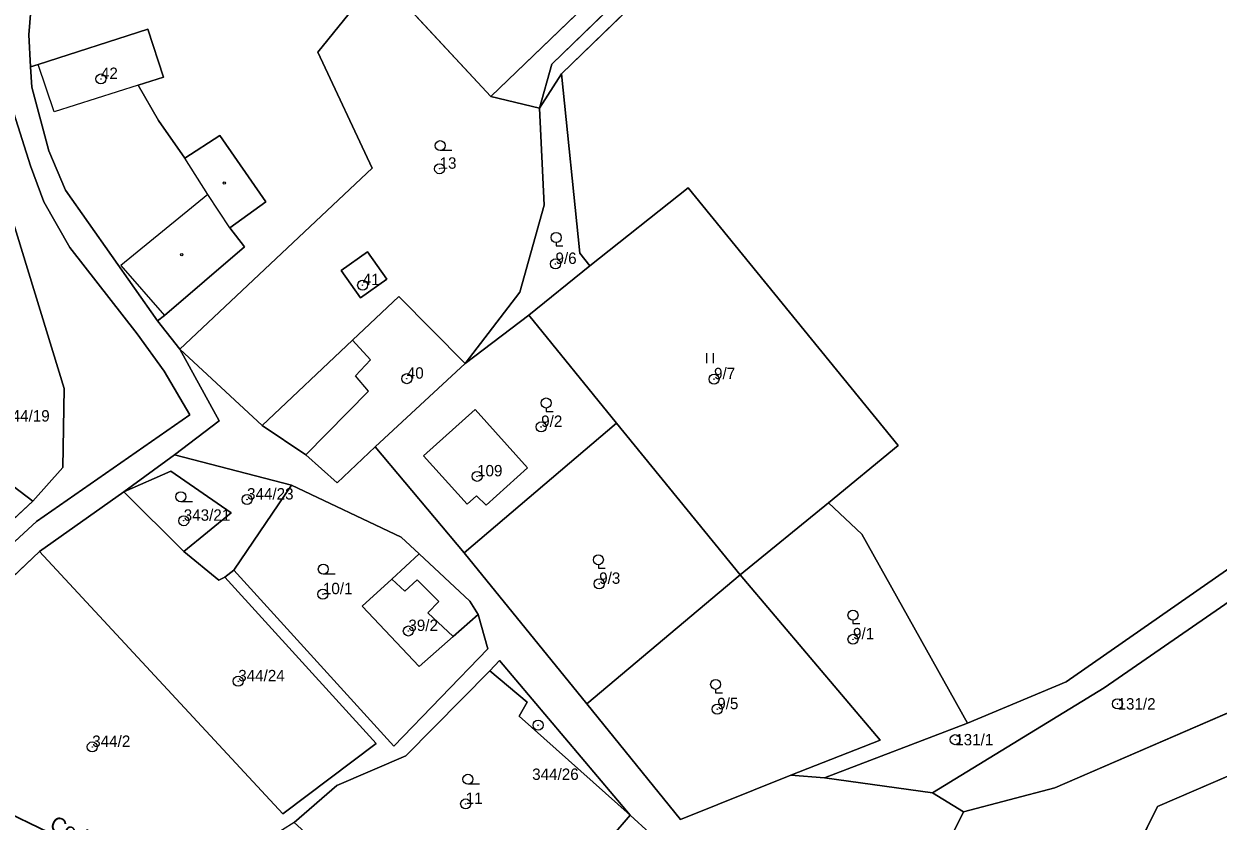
# Model space of a CAD drawing. Extents: x -652854 to -650068, y -1097661 to -1095417.
# Drawn here: x -650819.6 to -650641.1, y -1095957.3 to -1095838.2 of the extents above; entities that cross this region are included whole.
import ezdxf

# ---------------------------------------------------------------- set-up
doc = ezdxf.new("R2010")
doc.units = 0
for name, color, linetype in [('Definiční body parcel', 7, 'Continuous'), ('Hranice - vnitř_ kresba', 7, 'Continuous'), ('Hranice parcel', 7, 'Continuous'), ('Názvy', 7, 'Continuous'), ('Obvody jako plochy', 7, 'Continuous'), ('Parcelní čísla', 7, 'Continuous'), ('Prvky pro prodl_ par_ č_', 7, 'Continuous'), ('Značky kultur', 7, 'Continuous'), ('Značky na budově ne v SPI', 7, 'Continuous')]:
    doc.layers.add(name, color=color, linetype=linetype)

msp = doc.modelspace()

# ---------------------------------------------------------------- linework, layer by layer
at = {"layer": 'Definiční body parcel'}
for centre, radius in [((-650808.08, -1095846.43), 0.75), ((-650808.08, -1095846.43), 0.0327), ((-650757.46, -1095859.84), 0.75), ((-650757.46, -1095859.84), 0.0327), ((-650740.14, -1095874.06), 0.75), ((-650740.14, -1095874.06), 0.0327), ((-650768.96, -1095877.23), 0.75), ((-650768.96, -1095877.23), 0.0327), ((-650762.36, -1095891.2), 0.75), ((-650716.44, -1095891.27), 0.75), ((-650762.36, -1095891.2), 0.0327), ((-650716.44, -1095891.27), 0.0327), ((-650742.28, -1095898.4), 0.75), ((-650742.28, -1095898.4), 0.0327), ((-650751.86, -1095905.79), 0.75), ((-650751.86, -1095905.79), 0.0327), ((-650786.24, -1095909.25), 0.75), ((-650786.24, -1095909.25), 0.0327), ((-650795.7, -1095912.42), 0.75), ((-650795.7, -1095912.42), 0.0327), ((-650733.61, -1095921.84), 0.75), ((-650774.9, -1095923.39), 0.75), ((-650733.61, -1095921.84), 0.0327), ((-650774.9, -1095923.39), 0.0327), ((-650762.13, -1095928.89), 0.75), ((-650762.13, -1095928.89), 0.0327), ((-650695.67, -1095930.13), 0.75), ((-650695.67, -1095930.13), 0.0327), ((-650787.56, -1095936.4), 0.75), ((-650787.56, -1095936.4), 0.0327), ((-650715.96, -1095940.57), 0.75), ((-650715.96, -1095940.57), 0.0327), ((-650656.13, -1095939.77), 0.75), ((-650656.13, -1095939.77), 0.0327), ((-650742.74, -1095942.96), 0.75), ((-650742.74, -1095942.96), 0.0327), ((-650809.38, -1095946.2), 0.75), ((-650680.39, -1095945.12), 0.75), ((-650680.39, -1095945.12), 0.0327), ((-650809.38, -1095946.2), 0.0327), ((-650753.56, -1095954.72), 0.75), ((-650753.56, -1095954.72), 0.0327)]:
    msp.add_circle(centre, radius, dxfattribs=at)
at = {"layer": 'Hranice - vnitř_ kresba'}
for p, q in [((-650815.06, -1095851.32), (-650817.44, -1095844.26)), ((-650802.53, -1095847.35), (-650815.06, -1095851.32)), ((-650792.11, -1095863.7), (-650795.54, -1095858.28)), ((-650792.11, -1095863.7), (-650805.08, -1095874.27)), ((-650788.83, -1095868.66), (-650792.11, -1095863.7)), ((-650805.08, -1095874.27), (-650798.57, -1095881.77)), ((-650767.77, -1095888.38), (-650770.5, -1095885.45)), ((-650770.05, -1095890.78), (-650767.77, -1095888.38)), ((-650768.07, -1095893.06), (-650770.05, -1095890.78)), ((-650777.46, -1095902.58), (-650768.07, -1095893.06)), ((-650764.61, -1095921.13), (-650762.66, -1095922.94)), ((-650762.66, -1095922.94), (-650760.83, -1095921.27)), ((-650760.83, -1095921.27), (-650757.56, -1095924.49)), ((-650757.56, -1095924.49), (-650759.21, -1095926.2)), ((-650759.21, -1095926.2), (-650755.43, -1095929.71))]:
    msp.add_line(p, q, dxfattribs=at)
at = {"layer": 'Hranice parcel'}
for p, q in [((-650749.82, -1095849.06), (-650710.55, -1095811.33)), ((-650818.83, -1095839.82), (-650816.69, -1095813.37)), ((-650707.91, -1095812.42), (-650740.66, -1095844.24)), ((-650707.4, -1095814.79), (-650739.26, -1095845.66)), ((-650775.65, -1095842.44), (-650766.51, -1095831.07)), ((-650766.51, -1095831.07), (-650749.82, -1095849.06)), ((-650817.44, -1095844.26), (-650801.07, -1095838.98)), ((-650801.07, -1095838.98), (-650798.74, -1095846.16)), ((-650818.59, -1095844.63), (-650818.83, -1095839.82)), ((-650767.52, -1095859.75), (-650775.65, -1095842.44)), ((-650818.59, -1095844.63), (-650817.44, -1095844.26)), ((-650740.66, -1095844.24), (-650742.53, -1095850.77)), ((-650818.41, -1095847.67), (-650818.59, -1095844.63)), ((-650742.53, -1095850.77), (-650739.26, -1095845.66)), ((-650739.26, -1095845.66), (-650736.48, -1095872.46)), ((-650822.33, -1095847.63), (-650818.61, -1095859.41)), ((-650815.85, -1095857.15), (-650818.41, -1095847.67)), ((-650798.74, -1095846.16), (-650802.53, -1095847.35)), ((-650802.53, -1095847.35), (-650799.45, -1095852.64)), ((-650742.53, -1095850.77), (-650749.82, -1095849.06)), ((-650741.85, -1095865.29), (-650742.53, -1095850.77)), ((-650799.45, -1095852.64), (-650795.54, -1095858.28)), ((-650795.54, -1095858.28), (-650790.32, -1095854.86)), ((-650790.32, -1095854.86), (-650783.41, -1095864.8)), ((-650813.36, -1095863.05), (-650815.85, -1095857.15)), ((-650818.61, -1095859.41), (-650816.62, -1095864.78)), ((-650767.52, -1095859.75), (-650796.27, -1095886.77)), ((-650813.57, -1095892.69), (-650822.42, -1095863.74)), ((-650799.6, -1095882.56), (-650813.36, -1095863.05)), ((-650734.98, -1095874.35), (-650720.3, -1095862.69)), ((-650720.3, -1095862.69), (-650688.9, -1095901.19)), ((-650816.62, -1095864.78), (-650812.74, -1095871.62)), ((-650783.41, -1095864.8), (-650788.83, -1095868.66)), ((-650745.45, -1095878.26), (-650741.85, -1095865.29)), ((-650788.83, -1095868.66), (-650786.61, -1095871.49)), ((-650812.74, -1095871.62), (-650802.65, -1095884.5)), ((-650786.61, -1095871.49), (-650798.57, -1095881.77)), ((-650768.24, -1095872.24), (-650772.18, -1095875.06)), ((-650765.35, -1095876.35), (-650768.24, -1095872.24)), ((-650736.48, -1095872.46), (-650734.98, -1095874.35)), ((-650734.98, -1095874.35), (-650744.11, -1095881.7)), ((-650772.18, -1095875.06), (-650769.26, -1095879.11)), ((-650769.26, -1095879.11), (-650765.35, -1095876.35)), ((-650753.65, -1095888.94), (-650745.45, -1095878.26)), ((-650770.5, -1095885.45), (-650763.57, -1095878.9)), ((-650763.57, -1095878.9), (-650753.65, -1095888.94)), ((-650798.57, -1095881.77), (-650799.6, -1095882.56)), ((-650744.11, -1095881.7), (-650753.65, -1095888.94)), ((-650744.11, -1095881.7), (-650731, -1095897.82)), ((-650796.27, -1095886.77), (-650799.6, -1095882.56)), ((-650802.65, -1095884.5), (-650798.62, -1095890.09)), ((-650790.39, -1095897.52), (-650796.27, -1095886.77)), ((-650796.27, -1095886.77), (-650783.98, -1095898.17)), ((-650783.98, -1095898.17), (-650770.5, -1095885.45)), ((-650753.65, -1095888.94), (-650767.09, -1095901.36)), ((-650844.78, -1095889.35), (-650818.25, -1095909.52)), ((-650798.62, -1095890.09), (-650794.81, -1095896.6)), ((-650813.78, -1095904.48), (-650813.57, -1095892.69)), ((-650752.16, -1095895.79), (-650759.84, -1095902.7)), ((-650744.32, -1095904.5), (-650752.16, -1095895.79)), ((-650794.81, -1095896.6), (-650817.71, -1095912.52)), ((-650797.09, -1095902.55), (-650790.39, -1095897.52)), ((-650753.8, -1095917.19), (-650731, -1095897.82)), ((-650731, -1095897.82), (-650712.52, -1095920.49)), ((-650777.46, -1095902.58), (-650783.98, -1095898.17)), ((-650767.09, -1095901.36), (-650772.79, -1095906.75)), ((-650753.8, -1095917.19), (-650767.09, -1095901.36)), ((-650688.9, -1095901.19), (-650699.31, -1095909.75)), ((-650804.63, -1095908.11), (-650797.09, -1095902.55)), ((-650797.09, -1095902.55), (-650779.6, -1095907.12)), ((-650772.79, -1095906.75), (-650777.46, -1095902.58)), ((-650759.84, -1095902.7), (-650753.32, -1095909.94)), ((-650615.21, -1095902.66), (-650663.79, -1095936.46)), ((-650818.25, -1095909.52), (-650813.78, -1095904.48)), ((-650797.61, -1095905), (-650804.63, -1095908.11)), ((-650788.6, -1095911.24), (-650797.61, -1095905)), ((-650750.52, -1095910.09), (-650744.32, -1095904.5)), ((-650817.24, -1095917.02), (-650804.63, -1095908.11)), ((-650804.63, -1095908.11), (-650795.71, -1095917.03)), ((-650788.22, -1095919.78), (-650779.6, -1095907.12)), ((-650779.6, -1095907.12), (-650763.22, -1095914.85)), ((-650830.74, -1095921.05), (-650818.25, -1095909.52)), ((-650753.32, -1095909.94), (-650751.96, -1095908.72)), ((-650751.96, -1095908.72), (-650750.52, -1095910.09)), ((-650712.52, -1095920.49), (-650699.31, -1095909.75)), ((-650694.36, -1095914.44), (-650699.31, -1095909.75)), ((-650795.71, -1095917.03), (-650788.6, -1095911.24)), ((-650817.71, -1095912.52), (-650843.42, -1095936.19)), ((-650763.22, -1095914.85), (-650760.52, -1095917.37)), ((-650678.58, -1095942.65), (-650694.36, -1095914.44)), ((-650840.77, -1095939.29), (-650817.24, -1095917.02)), ((-650780.89, -1095956.2), (-650817.24, -1095917.02)), ((-650795.71, -1095917.03), (-650790.44, -1095921.28)), ((-650760.52, -1095917.37), (-650764.61, -1095921.13)), ((-650760.52, -1095917.37), (-650752.95, -1095924.41)), ((-650735.43, -1095939.77), (-650753.8, -1095917.19)), ((-650790.44, -1095921.28), (-650789.54, -1095920.86)), ((-650789.54, -1095920.86), (-650788.22, -1095919.78)), ((-650789.54, -1095920.86), (-650766.95, -1095945.69)), ((-650764.3, -1095946.11), (-650788.22, -1095919.78)), ((-650712.52, -1095920.49), (-650735.43, -1095939.77)), ((-650691.59, -1095945.18), (-650712.52, -1095920.49)), ((-650633.81, -1095920.58), (-650658.15, -1095937.4)), ((-650764.61, -1095921.13), (-650769.01, -1095925.17)), ((-650752.95, -1095924.41), (-650751.71, -1095926.43)), ((-650769.01, -1095925.17), (-650760.51, -1095934.19)), ((-650755.43, -1095929.71), (-650751.71, -1095926.43)), ((-650751.71, -1095926.43), (-650750.24, -1095931.56)), ((-650760.51, -1095934.19), (-650755.43, -1095929.71)), ((-650750.24, -1095931.56), (-650764.3, -1095946.11)), ((-650749.95, -1095934.85), (-650748.52, -1095933.28)), ((-650748.52, -1095933.28), (-650728.99, -1095956.42)), ((-650749.95, -1095934.85), (-650762.5, -1095947.53)), ((-650744.35, -1095939.5), (-650749.95, -1095934.85)), ((-650624.51, -1095934.57), (-650665.5, -1095952.31)), ((-650663.79, -1095936.46), (-650678.58, -1095942.65)), ((-650658.15, -1095937.4), (-650683.81, -1095953.04)), ((-650745.59, -1095941.61), (-650744.35, -1095939.5)), ((-650735.43, -1095939.77), (-650721.47, -1095957.06)), ((-650728.99, -1095956.42), (-650745.59, -1095941.61)), ((-650678.58, -1095942.65), (-650699.94, -1095950.82)), ((-650766.95, -1095945.69), (-650780.89, -1095956.2)), ((-650704.97, -1095950.42), (-650691.59, -1095945.18)), ((-650626.69, -1095945), (-650650.16, -1095955.09)), ((-650762.5, -1095947.53), (-650772.84, -1095951.98)), ((-650721.47, -1095957.06), (-650704.97, -1095950.42)), ((-650704.97, -1095950.42), (-650699.94, -1095950.82)), ((-650683.81, -1095953.04), (-650699.94, -1095950.82)), ((-650828.97, -1095952.68), (-650768.13, -1095982)), ((-650772.84, -1095951.98), (-650779.21, -1095957.51)), ((-650679.13, -1095955.92), (-650683.81, -1095953.04)), ((-650665.5, -1095952.31), (-650679.13, -1095955.92)), ((-650731.74, -1095959.61), (-650728.99, -1095956.42)), ((-650726.02, -1095959.09), (-650728.99, -1095956.42)), ((-650679.13, -1095955.92), (-650683.21, -1095964.08)), ((-650650.16, -1095955.09), (-650655.71, -1095966.27))]:
    msp.add_line(p, q, dxfattribs=at)
at = {"layer": 'Obvody jako plochy'}
for points in [[(-650715.92, -1095779.02), (-650707.91, -1095812.42), (-650740.66, -1095844.24), (-650742.53, -1095850.77), (-650739.26, -1095845.66), (-650707.4, -1095814.79), (-650699.64, -1095816.89), (-650709.03, -1095779.57), (-650692.25, -1095742.86)], [(-650715.92, -1095779.02), (-650733.52, -1095789.9), (-650720.49, -1095784.94), (-650710.55, -1095811.33), (-650749.82, -1095849.06), (-650742.53, -1095850.77), (-650740.66, -1095844.24), (-650707.91, -1095812.42)], [(-650749.82, -1095849.06), (-650710.55, -1095811.33), (-650720.49, -1095784.94), (-650733.52, -1095789.9), (-650762.13, -1095825.6), (-650766.51, -1095831.07)], [(-650822.33, -1095847.63), (-650821.45, -1095812.61), (-650825.74, -1095811.08), (-650838.32, -1095807.2), (-650848.05, -1095802.48), (-650850.5, -1095805.49), (-650871.31, -1095836.39), (-650885.3, -1095832.78), (-650888.99, -1095851.28), (-650843.17, -1095879.48), (-650857.68, -1095897.96), (-650846.23, -1095925.14), (-650850.06, -1095928.49), (-650843.42, -1095936.19), (-650817.71, -1095912.52), (-650794.81, -1095896.6), (-650798.62, -1095890.09), (-650802.65, -1095884.5), (-650812.74, -1095871.62), (-650816.62, -1095864.78), (-650818.61, -1095859.41)], [(-650742.53, -1095850.77), (-650749.82, -1095849.06), (-650766.51, -1095831.07), (-650775.65, -1095842.44), (-650767.52, -1095859.75), (-650796.27, -1095886.77), (-650783.98, -1095898.17), (-650770.5, -1095885.45), (-650763.57, -1095878.9), (-650753.65, -1095888.94), (-650745.45, -1095878.26), (-650741.85, -1095865.29)], [(-650813.36, -1095863.05), (-650799.6, -1095882.56), (-650798.57, -1095881.77), (-650786.61, -1095871.49), (-650788.83, -1095868.66), (-650783.41, -1095864.8), (-650790.32, -1095854.86), (-650795.54, -1095858.28), (-650799.45, -1095852.64), (-650802.53, -1095847.35), (-650798.74, -1095846.16), (-650801.07, -1095838.98), (-650817.44, -1095844.26), (-650818.59, -1095844.63), (-650818.41, -1095847.67), (-650815.85, -1095857.15)], [(-650742.53, -1095850.77), (-650741.85, -1095865.29), (-650745.45, -1095878.26), (-650753.65, -1095888.94), (-650744.11, -1095881.7), (-650734.98, -1095874.35), (-650736.48, -1095872.46), (-650739.26, -1095845.66)], [(-650830.74, -1095921.05), (-650844.06, -1095898.11), (-650844.78, -1095889.35), (-650831, -1095870.58), (-650822.42, -1095863.74), (-650813.57, -1095892.69), (-650813.78, -1095904.48), (-650818.25, -1095909.52)], [(-650844.78, -1095889.35), (-650818.25, -1095909.52), (-650813.78, -1095904.48), (-650813.57, -1095892.69), (-650822.42, -1095863.74), (-650831, -1095870.58)], [(-650734.98, -1095874.35), (-650744.11, -1095881.7), (-650731, -1095897.82), (-650712.52, -1095920.49), (-650699.31, -1095909.75), (-650688.9, -1095901.19), (-650720.3, -1095862.69)], [(-650768.24, -1095872.24), (-650772.18, -1095875.06), (-650769.26, -1095879.11), (-650765.35, -1095876.35)], [(-650768.24, -1095872.24), (-650765.35, -1095876.35), (-650769.26, -1095879.11), (-650772.18, -1095875.06)], [(-650777.46, -1095902.58), (-650772.79, -1095906.75), (-650767.09, -1095901.36), (-650753.65, -1095888.94), (-650763.57, -1095878.9), (-650770.5, -1095885.45), (-650783.98, -1095898.17)], [(-650744.11, -1095881.7), (-650753.65, -1095888.94), (-650767.09, -1095901.36), (-650753.8, -1095917.19), (-650731, -1095897.82)], [(-650830.74, -1095921.05), (-650818.25, -1095909.52), (-650844.78, -1095889.35), (-650844.06, -1095898.11)], [(-650752.16, -1095895.79), (-650759.84, -1095902.7), (-650753.32, -1095909.94), (-650751.96, -1095908.72), (-650750.52, -1095910.09), (-650744.32, -1095904.5)], [(-650752.16, -1095895.79), (-650744.32, -1095904.5), (-650750.52, -1095910.09), (-650751.96, -1095908.72), (-650753.32, -1095909.94), (-650759.84, -1095902.7)], [(-650735.43, -1095939.77), (-650712.52, -1095920.49), (-650731, -1095897.82), (-650753.8, -1095917.19)], [(-650602.74, -1095899.15), (-650615.21, -1095902.66), (-650663.79, -1095936.46), (-650678.58, -1095942.65), (-650699.94, -1095950.82), (-650683.81, -1095953.04), (-650658.15, -1095937.4), (-650633.81, -1095920.58)], [(-650797.61, -1095905), (-650788.6, -1095911.24), (-650795.71, -1095917.03), (-650790.44, -1095921.28), (-650789.54, -1095920.86), (-650788.22, -1095919.78), (-650779.6, -1095907.12), (-650797.09, -1095902.55), (-650804.63, -1095908.11)], [(-650797.61, -1095905), (-650804.63, -1095908.11), (-650795.71, -1095917.03), (-650788.6, -1095911.24)], [(-650817.24, -1095917.02), (-650780.89, -1095956.2), (-650766.95, -1095945.69), (-650789.54, -1095920.86), (-650790.44, -1095921.28), (-650795.71, -1095917.03), (-650804.63, -1095908.11)], [(-650779.6, -1095907.12), (-650788.22, -1095919.78), (-650764.3, -1095946.11), (-650750.24, -1095931.56), (-650751.71, -1095926.43), (-650755.43, -1095929.71), (-650760.51, -1095934.19), (-650769.01, -1095925.17), (-650764.61, -1095921.13), (-650760.52, -1095917.37), (-650763.22, -1095914.85)], [(-650704.97, -1095950.42), (-650699.94, -1095950.82), (-650678.58, -1095942.65), (-650694.36, -1095914.44), (-650699.31, -1095909.75), (-650712.52, -1095920.49), (-650691.59, -1095945.18)], [(-650760.52, -1095917.37), (-650764.61, -1095921.13), (-650769.01, -1095925.17), (-650760.51, -1095934.19), (-650755.43, -1095929.71), (-650751.71, -1095926.43), (-650752.95, -1095924.41)], [(-650704.97, -1095950.42), (-650691.59, -1095945.18), (-650712.52, -1095920.49), (-650735.43, -1095939.77), (-650721.47, -1095957.06)], [(-650624.51, -1095934.57), (-650633.81, -1095920.58), (-650658.15, -1095937.4), (-650683.81, -1095953.04), (-650679.13, -1095955.92), (-650665.5, -1095952.31)], [(-650749.95, -1095934.85), (-650744.35, -1095939.5), (-650745.59, -1095941.61), (-650728.99, -1095956.42), (-650748.52, -1095933.28)], [(-650779.21, -1095957.51), (-650772.12, -1095963.94), (-650768.45, -1095961.71), (-650765.09, -1095964.36), (-650758.42, -1095965.5), (-650751.99, -1095963.16), (-650731.74, -1095959.61), (-650728.99, -1095956.42), (-650745.59, -1095941.61), (-650744.35, -1095939.5), (-650749.95, -1095934.85), (-650762.5, -1095947.53), (-650772.84, -1095951.98)], [(-650681.34, -1095998.35), (-650674.69, -1096001.79), (-650675.32, -1096003.13), (-650663.2, -1096025.43), (-650655.69, -1095990.58), (-650655.71, -1095966.27), (-650650.16, -1095955.09), (-650626.69, -1095945), (-650627.52, -1095958.3), (-650612.04, -1095953.51), (-650623.58, -1095936.04), (-650624.51, -1095934.57), (-650665.5, -1095952.31), (-650679.13, -1095955.92), (-650683.21, -1095964.08), (-650673.46, -1095966.76), (-650685.7, -1095992.01), (-650687.25, -1095993.74), (-650697.45, -1096004.89), (-650687.41, -1096010.3)], [(-650613.9, -1096078.29), (-650593.69, -1096090.8), (-650580.06, -1096067.29), (-650611.4, -1096015.81), (-650627.52, -1095958.3), (-650626.69, -1095945), (-650650.16, -1095955.09), (-650655.71, -1095966.27), (-650655.69, -1095990.58), (-650663.2, -1096025.43), (-650644.26, -1096049.61)], [(-650779.21, -1095971.99), (-650730.24, -1095960.69), (-650726.02, -1095959.09), (-650728.99, -1095956.42), (-650731.74, -1095959.61), (-650751.99, -1095963.16), (-650758.42, -1095965.5), (-650765.09, -1095964.36), (-650768.45, -1095961.71), (-650772.12, -1095963.94), (-650779.21, -1095957.51), (-650787.92, -1095962.98)]]:
    msp.add_lwpolyline(points, close=True, dxfattribs=at)
for points in [[(-650840.77, -1095939.29), (-650817.24, -1095917.02), (-650804.63, -1095908.11), (-650797.09, -1095902.55), (-650790.39, -1095897.52), (-650796.27, -1095886.77), (-650799.6, -1095882.56), (-650813.36, -1095863.05), (-650815.85, -1095857.15), (-650818.41, -1095847.67), (-650818.59, -1095844.63), (-650818.83, -1095839.82), (-650816.69, -1095813.37), (-650820.19, -1095753.68)], [(-650816.69, -1095813.37), (-650818.83, -1095839.82), (-650818.59, -1095844.63), (-650817.44, -1095844.26), (-650801.07, -1095838.98), (-650798.74, -1095846.16), (-650802.53, -1095847.35), (-650799.45, -1095852.64), (-650795.54, -1095858.28), (-650790.32, -1095854.86), (-650783.41, -1095864.8), (-650788.83, -1095868.66), (-650786.61, -1095871.49), (-650798.57, -1095881.77), (-650799.6, -1095882.56), (-650796.27, -1095886.77), (-650767.52, -1095859.75), (-650775.65, -1095842.44), (-650766.51, -1095831.07)], [(-650707.4, -1095814.79), (-650739.26, -1095845.66), (-650736.48, -1095872.46), (-650734.98, -1095874.35), (-650720.3, -1095862.69), (-650688.9, -1095901.19), (-650699.31, -1095909.75), (-650694.36, -1095914.44), (-650678.58, -1095942.65), (-650663.79, -1095936.46), (-650615.21, -1095902.66), (-650602.74, -1095899.15), (-650540.62, -1095861.56), (-650511.07, -1095852.45), (-650505.7, -1095846.33), (-650504.91, -1095834.49)], [(-650822.33, -1095847.63), (-650818.61, -1095859.41), (-650816.62, -1095864.78), (-650812.74, -1095871.62), (-650802.65, -1095884.5), (-650798.62, -1095890.09), (-650794.81, -1095896.6), (-650817.71, -1095912.52), (-650843.42, -1095936.19)], [(-650683.21, -1095964.08), (-650679.13, -1095955.92), (-650683.81, -1095953.04), (-650699.94, -1095950.82), (-650704.97, -1095950.42), (-650721.47, -1095957.06), (-650735.43, -1095939.77), (-650753.8, -1095917.19), (-650767.09, -1095901.36), (-650772.79, -1095906.75), (-650777.46, -1095902.58), (-650783.98, -1095898.17), (-650796.27, -1095886.77), (-650790.39, -1095897.52), (-650797.09, -1095902.55), (-650779.6, -1095907.12), (-650763.22, -1095914.85), (-650760.52, -1095917.37), (-650752.95, -1095924.41), (-650751.71, -1095926.43), (-650750.24, -1095931.56), (-650764.3, -1095946.11), (-650788.22, -1095919.78), (-650789.54, -1095920.86), (-650766.95, -1095945.69), (-650780.89, -1095956.2), (-650817.24, -1095917.02), (-650840.77, -1095939.29)], [(-650779.21, -1095957.51), (-650772.84, -1095951.98), (-650762.5, -1095947.53), (-650749.95, -1095934.85), (-650748.52, -1095933.28), (-650728.99, -1095956.42), (-650726.02, -1095959.09)], [(-650831.59, -1095955.54), (-650760.98, -1095990.15), (-650750.01, -1095996.81), (-650746.17, -1096002.75), (-650743.08, -1096007.04), (-650728.36, -1096020.69), (-650747.53, -1096038.65), (-650743.68, -1096050.84), (-650710.34, -1096086.58), (-650684.46, -1096102.07), (-650669.86, -1096109.7), (-650667.86, -1096108.56), (-650679.87, -1096100.67), (-650694.62, -1096091.37), (-650707.9, -1096083.31), (-650739.3, -1096051), (-650742.42, -1096039.7), (-650723.31, -1096020.21), (-650738.82, -1096004.52), (-650743.14, -1095998.82), (-650759, -1095989.33), (-650768.13, -1095982), (-650828.97, -1095952.68)], [(-650828.97, -1095952.68), (-650768.13, -1095982)]]:
    msp.add_lwpolyline(points, dxfattribs=at)
at = {"layer": 'Značky kultur'}
for p, q in [((-650755.61, -1095857.14), (-650757.36, -1095857.14)), ((-650740.04, -1095870.86), (-650740.04, -1095871.36)), ((-650740.04, -1095871.36), (-650739.017, -1095871.36)), ((-650717.557, -1095887.375), (-650717.557, -1095888.875)), ((-650716.535, -1095888.875), (-650716.535, -1095887.375)), ((-650741.53, -1095895.58), (-650741.53, -1095896.08)), ((-650741.53, -1095896.08), (-650740.507, -1095896.08)), ((-650794.38, -1095909.58), (-650796.13, -1095909.58)), ((-650733.73, -1095919), (-650733.73, -1095919.5)), ((-650773.09, -1095920.41), (-650774.84, -1095920.41)), ((-650733.73, -1095919.5), (-650732.707, -1095919.5)), ((-650695.67, -1095927.28), (-650695.67, -1095927.78)), ((-650695.67, -1095927.78), (-650694.647, -1095927.78)), ((-650716.2, -1095937.61), (-650716.2, -1095938.11)), ((-650716.2, -1095938.11), (-650715.177, -1095938.11)), ((-650751.47, -1095951.79), (-650753.22, -1095951.79))]:
    msp.add_line(p, q, dxfattribs=at)
for centre in [(-650757.36, -1095856.39), (-650740.04, -1095870.11), (-650741.53, -1095894.83), (-650796.13, -1095908.83), (-650733.73, -1095918.25), (-650774.84, -1095919.66), (-650695.67, -1095926.53), (-650716.2, -1095936.86), (-650753.22, -1095951.04)]:
    msp.add_circle(centre, 0.75, dxfattribs=at)
at = {"layer": 'Značky na budově ne v SPI'}
for centre in [(-650789.65, -1095861.99), (-650796.01, -1095872.69)]:
    msp.add_circle(centre, 0.175, dxfattribs=at)

# ---------------------------------------------------------------- texts
at = {"layer": 'Názvy'}
msp.add_text('Cerhovka', height=2.3, rotation=335.11959, dxfattribs=at).set_placement((-650815.904, -1095958.463))
at = {"layer": 'Parcelní čísla'}
for s, height, p in [('42', 1.7, (-650808.08, -1095846.43)), ('13', 1.7, (-650757.46, -1095859.84)), ('9/6', 1.7, (-650740.14, -1095874.06)), ('41', 1.7, (-650768.96, -1095877.23)), ('40', 1.7, (-650762.36, -1095891.2)), ('9/7', 1.7, (-650716.44, -1095891.27)), ('344/19', 1.7, (-650822.69, -1095897.6)), ('9/2', 1.7, (-650742.28, -1095898.4)), ('109', 1.7, (-650751.86, -1095905.79)), ('344/23', 1.7, (-650786.24, -1095909.25)), ('343/21', 1.7, (-650795.7, -1095912.42)), ('9/3', 1.7, (-650733.61, -1095921.84)), ('10/1', 1.7, (-650774.9, -1095923.39)), ('39/2', 1.7, (-650762.13, -1095928.89)), ('9/1', 1.7, (-650695.67, -1095930.13)), ('344/24', 1.7, (-650787.56, -1095936.4)), ('9/5', 1.7, (-650715.96, -1095940.57)), ('131/2', 1.7, (-650656.13, -1095940.62)), ('344/26', 0.1, (-650742.74, -1095942.96)), ('131/1', 1.7, (-650680.39, -1095945.97)), ('344/2', 1.7, (-650809.38, -1095946.2)), ('11', 1.7, (-650753.56, -1095954.72))]:
    msp.add_text(s, height=height, dxfattribs=at).set_placement(p)
at = {"layer": 'Prvky pro prodl_ par_ č_'}
msp.add_text('344/26', height=1.7, dxfattribs=at).set_placement((-650743.622, -1095951.13))

doc.saveas('drawing.dxf')
